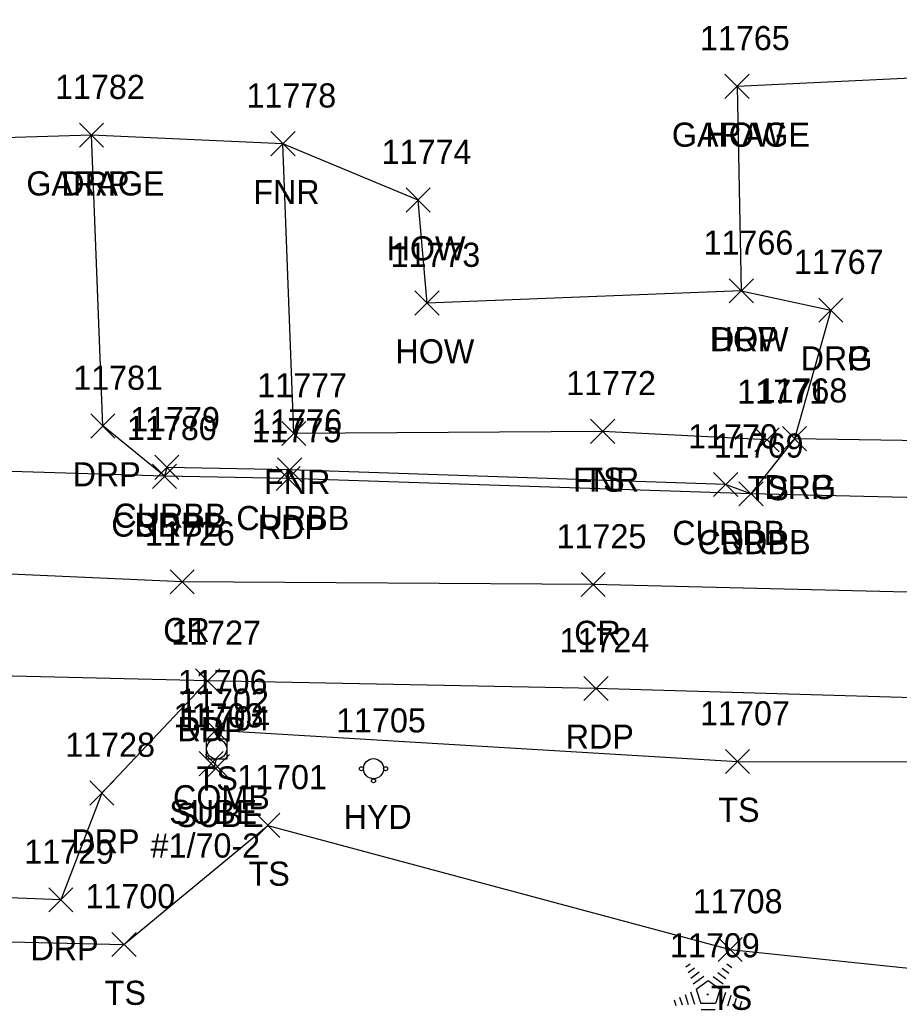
# Model space of a CAD drawing. Extents: x 1769141 to 1770911, y 735471 to 741449.
# Drawn here: x 1770709.9 to 1770782.8, y 738021 to 738103.3 of the extents above; entities that cross this region are included whole.
import ezdxf

# ---------------------------------------------------------------- set-up
doc = ezdxf.new("R2010")
doc.units = 0
for name, color, linetype in [('L_A', 7, 'Continuous'), ('L_I', 7, 'Continuous'), ('L_TIC', 7, 'Continuous'), ('LBC', 7, 'Continuous'), ('LELB', 7, 'Continuous'), ('LFNC', 7, 'Continuous'), ('LSOGP', 7, 'Continuous'), ('LTC', 7, 'Continuous'), ('P_A', 7, 'Continuous'), ('P_I', 7, 'Continuous'), ('P_TIC', 7, 'Continuous'), ('PET', 7, 'Continuous'), ('PRC', 7, 'Continuous'), ('R_A', 7, 'Continuous'), ('R_I', 7, 'Continuous'), ('R_TIC', 7, 'Continuous'), ('RC', 7, 'Continuous'), ('RDG', 7, 'Continuous'), ('RDP', 7, 'Continuous'), ('U_A', 7, 'Continuous'), ('U_C', 7, 'Continuous'), ('U_I', 7, 'Continuous'), ('U_TIC', 7, 'Continuous'), ('UP', 7, 'Continuous'), ('UWFH', 7, 'Continuous')]:
    doc.layers.add(name, color=color, linetype=linetype)

msp = doc.modelspace()

# ---------------------------------------------------------------- linework, layer by layer
at = {"layer": 'L_TIC'}
for points in [[(1770768.356, 738096.834), (1770770.356, 738098.834)], [(1770770.356, 738096.834), (1770768.356, 738098.834)], [(1770768.356, 738096.834), (1770770.356, 738098.834)], [(1770770.356, 738096.834), (1770768.356, 738098.834)], [(1770714.864, 738092.792), (1770716.864, 738094.792)], [(1770716.864, 738092.792), (1770714.864, 738094.792)], [(1770730.728, 738092.082), (1770732.728, 738094.082)], [(1770732.728, 738092.082), (1770730.728, 738094.082)], [(1770741.93, 738087.415), (1770743.93, 738089.415)], [(1770743.93, 738087.415), (1770741.93, 738089.415)], [(1770768.708, 738079.893), (1770770.708, 738081.893)], [(1770770.708, 738079.893), (1770768.708, 738081.893)], [(1770742.664, 738078.881), (1770744.664, 738080.881)], [(1770744.664, 738078.881), (1770742.664, 738080.881)], [(1770731.623, 738068.073), (1770733.623, 738070.073)], [(1770733.623, 738068.073), (1770731.623, 738070.073)], [(1770757.22, 738068.252), (1770759.22, 738070.252)], [(1770759.22, 738068.252), (1770757.22, 738070.252)], [(1770757.22, 738068.252), (1770759.22, 738070.252)], [(1770759.22, 738068.252), (1770757.22, 738070.252)], [(1770770.834, 738067.546), (1770772.834, 738069.546)], [(1770772.834, 738067.546), (1770770.834, 738069.546)], [(1770725.164, 738043.493), (1770727.164, 738045.493)], [(1770727.164, 738043.493), (1770725.164, 738045.493)], [(1770768.396, 738040.896), (1770770.396, 738042.896)], [(1770770.396, 738040.896), (1770768.396, 738042.896)], [(1770729.466, 738035.605), (1770731.466, 738037.605)], [(1770731.466, 738035.605), (1770729.466, 738037.605)], [(1770717.549, 738025.738), (1770719.549, 738027.738)], [(1770719.549, 738025.738), (1770717.549, 738027.738)], [(1770767.789, 738025.321), (1770769.789, 738027.321)], [(1770769.789, 738025.321), (1770767.789, 738027.321)]]:
    msp.add_lwpolyline(points, dxfattribs=at)
at = {"layer": 'LBC'}
for points in [[(1770819.14, 738103.343), (1770808.645, 738102.704), (1770809.13, 738100.712), (1770797.042, 738099.149), (1770769.356, 738097.834)], [(1770715.864, 738093.792), (1770691.376, 738093.033), (1770690.889, 738100.762)], [(1770769.356, 738097.834), (1770769.708, 738080.893), (1770743.664, 738079.881), (1770742.93, 738088.415)]]:
    msp.add_lwpolyline(points, dxfattribs=at)
at = {"layer": 'LELB'}
for points in [[(1770771.834, 738068.546), (1770758.22, 738069.252)], [(1770726.164, 738044.493), (1770769.396, 738041.896), (1770813.181, 738041.841), (1770841.977, 738042.223), (1770846.14, 738007.434), (1770845.64, 737990.94)], [(1770662.003, 738031.165), (1770679.85, 738027.659), (1770718.549, 738026.738), (1770730.466, 738036.605), (1770768.789, 738026.321), (1770809.249, 738022.102)]]:
    msp.add_lwpolyline(points, dxfattribs=at)
at = {"layer": 'LFNC'}
msp.add_lwpolyline([(1770758.22, 738069.252), (1770732.623, 738069.073), (1770731.728, 738093.082)], dxfattribs=at)
at = {"layer": 'LSOGP'}
msp.add_lwpolyline([(1770846.14, 738007.434), (1770842.773, 738039.035), (1770841.977, 738042.223), (1770843.577, 738045.406), (1770843.812, 738054.401), (1770847.137, 738061.752), (1770847.239, 738062.598), (1770847.38, 738064.906), (1770847.519, 738069.125), (1770845.15, 738077.024), (1770831.526, 738092.169), (1770819.14, 738103.343), (1770808.645, 738102.704), (1770809.13, 738100.712), (1770797.042, 738099.149), (1770769.356, 738097.834), (1770769.708, 738080.893), (1770743.664, 738079.881), (1770742.93, 738088.415), (1770731.728, 738093.082), (1770715.864, 738093.792), (1770691.376, 738093.033)], dxfattribs=at)
at = {"layer": 'LTC'}
for p, q in [((1770765.104, 738024.882), (1770765.459, 738025.14)), ((1770765.314, 738024.417), (1770765.843, 738024.801)), ((1770768.131, 738024.774), (1770768.681, 738024.375)), ((1770768.503, 738025.123), (1770768.922, 738024.818)), ((1770765.523, 738023.951), (1770766.227, 738024.462)), ((1770765.733, 738023.485), (1770766.611, 738024.123)), ((1770767.389, 738024.078), (1770768.199, 738023.489)), ((1770767.761, 738024.426), (1770768.44, 738023.932)), ((1770765.958, 738023.03), (1770766.969, 738023.765)), ((1770766.969, 738023.765), (1770767.966, 738023.04)), ((1770764.592, 738022.378), (1770764.804, 738021.726)), ((1770765.048, 738022.595), (1770765.319, 738021.759)), ((1770765.503, 738022.811), (1770765.834, 738021.792)), ((1770765.958, 738023.03), (1770766.345, 738021.837)), ((1770767.966, 738023.04), (1770767.575, 738021.837)), ((1770768.404, 738022.769), (1770768.066, 738021.729)), ((1770768.848, 738022.518), (1770768.561, 738021.634)), ((1770769.293, 738022.268), (1770769.056, 738021.539)), ((1770764.137, 738022.161), (1770764.289, 738021.693)), ((1770767.575, 738021.837), (1770766.345, 738021.837)), ((1770769.737, 738022.018), (1770769.551, 738021.444)), ((1770767.537, 738021.337), (1770766.392, 738021.337))]:
    msp.add_line(p, q, dxfattribs=at)
at = {"layer": 'P_TIC'}
for points in [[(1770720.916, 738064.526), (1770722.916, 738066.526)], [(1770722.916, 738064.526), (1770720.916, 738066.526)], [(1770731.151, 738064.345), (1770733.151, 738066.345)], [(1770733.151, 738064.345), (1770731.151, 738066.345)], [(1770769.509, 738063.076), (1770771.509, 738065.076)], [(1770771.509, 738063.076), (1770769.509, 738065.076)], [(1770722.367, 738055.792), (1770724.367, 738057.792)], [(1770724.367, 738055.792), (1770722.367, 738057.792)], [(1770756.427, 738055.561), (1770758.427, 738057.561)], [(1770758.427, 738055.561), (1770756.427, 738057.561)], [(1770724.491, 738047.574), (1770726.491, 738049.574)], [(1770726.491, 738047.574), (1770724.491, 738049.574)], [(1770756.667, 738046.953), (1770758.667, 738048.953)], [(1770758.667, 738046.953), (1770756.667, 738048.953)]]:
    msp.add_lwpolyline(points, dxfattribs=at)
at = {"layer": 'PET'}
for points in [[(1770847.137, 738061.752), (1770813.421, 738062.818), (1770792.774, 738063.549), (1770770.509, 738064.076), (1770732.151, 738065.345), (1770721.916, 738065.526), (1770685.588, 738066.648), (1770653.785, 738067.822), (1770624.403, 738070.472), (1770603.596, 738072.27), (1770595.136, 738073.286)], [(1770843.577, 738045.406), (1770800.896, 738046.668), (1770757.667, 738047.953), (1770725.491, 738048.574), (1770687.419, 738049.505), (1770662.563, 738051), (1770652.029, 738051.723), (1770624.846, 738053.021), (1770607.521, 738053.571), (1770596.745, 738055.56)]]:
    msp.add_lwpolyline(points, dxfattribs=at)
at = {"layer": 'PRC'}
msp.add_lwpolyline([(1770843.812, 738054.401), (1770801.56, 738055.494), (1770757.427, 738056.561), (1770723.367, 738056.792), (1770686.801, 738058.402), (1770653.871, 738059.602), (1770624.145, 738061.706), (1770597.498, 738064.454)], dxfattribs=at)
at = {"layer": 'R_TIC'}
for points in [[(1770714.864, 738092.792), (1770716.864, 738094.792)], [(1770716.864, 738092.792), (1770714.864, 738094.792)], [(1770768.708, 738079.893), (1770770.708, 738081.893)], [(1770770.708, 738079.893), (1770768.708, 738081.893)], [(1770776.136, 738078.298), (1770778.136, 738080.298)], [(1770778.136, 738078.298), (1770776.136, 738080.298)], [(1770776.136, 738078.298), (1770778.136, 738080.298)], [(1770778.136, 738078.298), (1770776.136, 738080.298)], [(1770715.803, 738068.696), (1770717.803, 738070.696)], [(1770717.803, 738068.696), (1770715.803, 738070.696)], [(1770773.126, 738067.642), (1770775.126, 738069.642)], [(1770775.126, 738067.642), (1770773.126, 738069.642)], [(1770773.126, 738067.642), (1770775.126, 738069.642)], [(1770775.126, 738067.642), (1770773.126, 738069.642)], [(1770721.096, 738065.267), (1770723.096, 738067.267)], [(1770723.096, 738065.267), (1770721.096, 738067.267)], [(1770731.278, 738065.07), (1770733.278, 738067.07)], [(1770733.278, 738065.07), (1770731.278, 738067.07)], [(1770720.916, 738064.526), (1770722.916, 738066.526)], [(1770722.916, 738064.526), (1770720.916, 738066.526)], [(1770720.916, 738064.526), (1770722.916, 738066.526)], [(1770722.916, 738064.526), (1770720.916, 738066.526)], [(1770767.41, 738063.844), (1770769.41, 738065.844)], [(1770769.41, 738063.844), (1770767.41, 738065.844)], [(1770769.509, 738063.076), (1770771.509, 738065.076)], [(1770771.509, 738063.076), (1770769.509, 738065.076)], [(1770769.509, 738063.076), (1770771.509, 738065.076)], [(1770771.509, 738063.076), (1770769.509, 738065.076)], [(1770724.491, 738047.574), (1770726.491, 738049.574)], [(1770726.491, 738047.574), (1770724.491, 738049.574)], [(1770715.709, 738038.287), (1770717.709, 738040.287)], [(1770717.709, 738038.287), (1770715.709, 738040.287)], [(1770712.317, 738029.432), (1770714.317, 738031.432)], [(1770714.317, 738029.432), (1770712.317, 738031.432)]]:
    msp.add_lwpolyline(points, dxfattribs=at)
at = {"layer": 'RC'}
msp.add_lwpolyline([(1770770.509, 738064.076), (1770768.41, 738064.844), (1770732.278, 738066.07), (1770722.096, 738066.267), (1770721.916, 738065.526)], dxfattribs=at)
at = {"layer": 'RDG'}
msp.add_lwpolyline([(1770777.136, 738079.298), (1770774.126, 738068.642)], dxfattribs=at)
at = {"layer": 'RDP'}
for points in [[(1770721.916, 738065.526), (1770716.803, 738069.696), (1770715.864, 738093.792)], [(1770769.708, 738080.893), (1770777.136, 738079.298)], [(1770792.774, 738063.549), (1770790.194, 738068.38), (1770774.126, 738068.642), (1770770.509, 738064.076)], [(1770725.491, 738048.574), (1770716.709, 738039.287), (1770713.317, 738030.432), (1770688.344, 738031.4), (1770666.239, 738032.094), (1770664.648, 738046.302), (1770662.563, 738051)]]:
    msp.add_lwpolyline(points, dxfattribs=at)
at = {"layer": 'U_TIC'}
for points in [[(1770724.77, 738040.723), (1770726.77, 738042.723)], [(1770726.77, 738040.723), (1770724.77, 738042.723)], [(1770725.3, 738040.471), (1770727.3, 738042.471)], [(1770727.3, 738040.471), (1770725.3, 738042.471)]]:
    msp.add_lwpolyline(points, dxfattribs=at)
at = {"layer": 'UP'}
for p, q in [((1770726.48, 738044.605), (1770726.23, 738043.771)), ((1770725.396, 738042.105), (1770725.396, 738043.771)), ((1770725.396, 738043.771), (1770727.063, 738043.771)), ((1770727.063, 738043.771), (1770727.063, 738042.105)), ((1770726.23, 738042.938), (1770726.23, 738042.938)), ((1770727.063, 738042.105), (1770725.396, 738042.105)), ((1770725.98, 738041.271), (1770726.23, 738042.105))]:
    msp.add_line(p, q, dxfattribs=at)
msp.add_circle((1770726.23, 738042.938), 0.833, dxfattribs=at)
at = {"layer": 'UWFH'}
msp.add_line((1770739.231, 738041.303), (1770739.231, 738041.303), dxfattribs=at)
for centre, radius in [((1770739.231, 738041.303), 0.833), ((1770738.231, 738041.303), 0.167), ((1770740.231, 738041.303), 0.167), ((1770739.231, 738040.303), 0.167)]:
    msp.add_circle(centre, radius, dxfattribs=at)

# ---------------------------------------------------------------- texts
at = {"layer": 'L_A'}
for s, p in [('GARAGE', (1770763.955, 738092.834)), ('HOW', (1770766.742, 738092.834)), ('GARAGE', (1770710.463, 738088.792)), ('FNR', (1770729.263, 738088.082)), ('HOW', (1770740.316, 738083.415)), ('HOW', (1770767.093, 738075.893)), ('HOW', (1770741.049, 738074.881)), ('FNR', (1770730.158, 738064.073)), ('FNR', (1770755.756, 738064.252)), ('TS', (1770756.63, 738064.252)), ('TS', (1770770.243, 738063.546)), ('TS', (1770724.573, 738039.493)), ('TS', (1770767.805, 738036.896)), ('TS', (1770728.875, 738031.605)), ('TS', (1770716.959, 738021.738)), ('TS', (1770767.199, 738021.321))]:
    msp.add_text(s, height=2, dxfattribs=at).set_placement(p)
at = {"layer": 'L_I'}
for s, p in [('11765', (1770766.285, 738100.834)), ('11765', (1770766.285, 738100.834)), ('11782', (1770712.841, 738096.792)), ('11778', (1770728.704, 738096.082)), ('11774', (1770739.907, 738091.415)), ('11766', (1770766.582, 738083.893)), ('11773', (1770740.64, 738082.881)), ('11772', (1770755.197, 738072.252)), ('11772', (1770755.197, 738072.252)), ('11777', (1770729.599, 738072.073)), ('11771', (1770769.377, 738071.546)), ('11706', (1770723.006, 738047.493)), ('11707', (1770766.294, 738044.896)), ('11701', (1770727.93, 738039.605)), ('11700', (1770715.36, 738029.738)), ('11708', (1770765.687, 738029.321)), ('11709', (1770763.799, 738025.674))]:
    msp.add_text(s, height=2, dxfattribs=at).set_placement(p)
at = {"layer": 'LTC'}
msp.add_text('.', height=1.037, rotation=270, dxfattribs=at).set_placement((1770766.852, 738022.778))
at = {"layer": 'P_A'}
for s, p in [('RDP', (1770719.404, 738060.526)), ('RDP', (1770729.639, 738060.345)), ('RDP', (1770767.997, 738059.076)), ('CR', (1770721.8, 738051.792)), ('CR', (1770755.86, 738051.561)), ('RDP', (1770722.979, 738043.574)), ('RDP', (1770755.156, 738042.953))]:
    msp.add_text(s, height=2, dxfattribs=at).set_placement(p)
at = {"layer": 'P_I'}
for s, p in [('11780', (1770718.805, 738068.526)), ('11775', (1770729.128, 738068.345)), ('11769', (1770767.43, 738067.076)), ('11726', (1770720.288, 738059.792)), ('11725', (1770754.403, 738059.561)), ('11727', (1770722.467, 738051.574)), ('11724', (1770754.644, 738050.953))]:
    msp.add_text(s, height=2, dxfattribs=at).set_placement(p)
at = {"layer": 'R_A'}
for s, p in [('DRP', (1770713.352, 738088.792)), ('DRP', (1770767.196, 738075.893)), ('DRG', (1770774.624, 738074.298)), ('DRP', (1770774.624, 738074.298)), ('DRP', (1770714.291, 738064.696)), ('DRG', (1770771.615, 738063.642)), ('DRP', (1770771.615, 738063.642)), ('CURBB', (1770717.678, 738061.267)), ('CURBB', (1770727.861, 738061.07)), ('CURBB', (1770717.498, 738060.526)), ('DRP', (1770719.404, 738060.526)), ('CURBB', (1770763.993, 738059.844)), ('CURBB', (1770766.092, 738059.076)), ('DRP', (1770767.997, 738059.076)), ('DRP', (1770722.979, 738043.574)), ('DRP', (1770714.197, 738034.287)), ('DRP', (1770710.805, 738025.432))]:
    msp.add_text(s, height=2, dxfattribs=at).set_placement(p)
at = {"layer": 'R_I'}
for s, p in [('11782', (1770712.841, 738096.792)), ('11766', (1770766.582, 738083.893)), ('11767', (1770774.065, 738082.298)), ('11767', (1770774.065, 738082.298)), ('11781', (1770714.346, 738072.696)), ('11768', (1770771.055, 738071.642)), ('11768', (1770771.055, 738071.642)), ('11779', (1770719.064, 738069.267)), ('11776', (1770729.199, 738069.07)), ('11780', (1770718.805, 738068.526)), ('11780', (1770718.805, 738068.526)), ('11770', (1770765.3, 738067.844)), ('11769', (1770767.43, 738067.076)), ('11769', (1770767.43, 738067.076)), ('11727', (1770722.467, 738051.574)), ('11728', (1770713.685, 738042.287)), ('11729', (1770710.285, 738033.432))]:
    msp.add_text(s, height=2, dxfattribs=at).set_placement(p)
at = {"layer": 'U_A'}
for s, p in [('COMB', (1770722.615, 738037.938)), ('SUBE', (1770722.305, 738036.723)), ('SUBE', (1770722.836, 738036.471)), ('HYD', (1770736.751, 738036.303))]:
    msp.add_text(s, height=2, dxfattribs=at).set_placement(p)
at = {"layer": 'U_C'}
msp.add_text('#1/70-2', height=2, dxfattribs=at).set_placement((1770720.765, 738033.938))
at = {"layer": 'U_I'}
for s, p in [('11702', (1770723.127, 738045.938)), ('11703', (1770722.667, 738044.723)), ('11704', (1770723.198, 738044.471)), ('11705', (1770736.129, 738044.303))]:
    msp.add_text(s, height=2, dxfattribs=at).set_placement(p)

doc.saveas('drawing.dxf')
